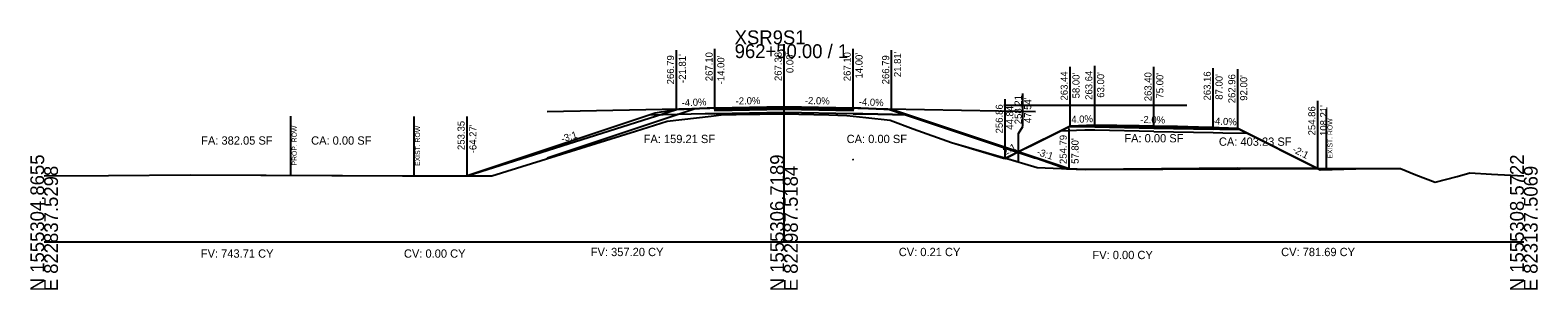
# Model space of a CAD drawing. Extents: x -26 to 823017, y -16 to 1558356.
# Drawn here: x 997.2 to 1302.8, y 1490.3 to 1542.8 of the extents above; entities that cross this region are included whole.
import ezdxf

# ---------------------------------------------------------------- set-up
doc = ezdxf.new("R2010")
doc.units = 0
for name, color, linetype in [('ASPHALT_19MM1', 7, 'Continuous'), ('ASPHALT_9_5MM1', 7, 'Continuous'), ('CONST_DCH', 7, 'Continuous'), ('CONST_LV3', 7, 'Continuous'), ('Default', 7, 'Continuous'), ('Draft_XS_Grid', 7, 'Continuous'), ('DTM_CORRIDOR', 7, 'Continuous'), ('DTM_P_FINISHED_GRADE2', 7, 'Continuous'), ('DTM_TEMP_DROP', 7, 'Continuous'), ('DTM_X_GROUND', 7, 'Continuous'), ('PROFILES_DCH_2', 7, 'Continuous'), ('SLOPE_STAKES_FILL', 7, 'Continuous'), ('XS_CELL', 7, 'Continuous'), ('XS_M_SHAPES_EARTHWORK', 7, 'Continuous'), ('XS_P_ASPHALT', 7, 'Continuous'), ('XS_P_DR_GRAVEL', 7, 'Continuous'), ('XS_P_GROUND', 7, 'Continuous'), ('XS_P_NULL_POINT', 7, 'Continuous'), ('XS_P_ROW', 7, 'Continuous'), ('XS_P_SHOULDER', 7, 'Continuous'), ('XS_P_SUBGRADE_GRANULAR', 7, 'Continuous'), ('XS_P_SUBGRADE_MILLING', 7, 'Continuous'), ('XS_P_SUBGRADE_UNDERCUT', 7, 'Continuous'), ('XS_P_TX_CLEARZONE', 7, 'Continuous'), ('XS_P_TX_FS_BS', 7, 'Continuous'), ('XS_SHEET_EW_TX_AREA', 7, 'Continuous'), ('XS_SHEET_EW_TX_VOLUME', 7, 'Continuous'), ('XS_X_ROW', 7, 'Continuous')]:
    doc.layers.add(name, color=color, linetype=linetype)

msp = doc.modelspace()

# ---------------------------------------------------------------- linework, layer by layer
at = {"layer": 'ASPHALT_19MM1'}
for points in [[(1136, 1526.81), (1136, 1526.6), (1150, 1526.88), (1150, 1526.88), (1150, 1526.88), (1164, 1526.6), (1164, 1526.81), (1164, 1526.81), (1150, 1527.09), (1150, 1527.09), (1150, 1527.09), (1136, 1526.81), (1136, 1526.81)], [(1213, 1523.27), (1225, 1523.03), (1237, 1522.79), (1237, 1523), (1225, 1523.24), (1213, 1523.48), (1213, 1523.27)]]:
    msp.add_lwpolyline(points, dxfattribs=at)
at = {"layer": 'ASPHALT_9_5MM1'}
msp.add_lwpolyline([(1136, 1527.1), (1150, 1527.38), (1150, 1527.38), (1150, 1527.38), (1164, 1527.1), (1164, 1526.98), (1150, 1527.26), (1150, 1527.26), (1150, 1527.26), (1136, 1526.98), (1136, 1527.1)], dxfattribs=at)
at = {"layer": 'CONST_DCH'}
msp.add_lwpolyline([(1213, 1523.48), (1225, 1523.24), (1237, 1523), (1237, 1523.16), (1225, 1523.4), (1213, 1523.64), (1213, 1523.48)], dxfattribs=at)
at = {"layer": 'CONST_LV3'}
for points in [[(1102, 1526.42), (1132, 1527.02), (1150, 1527.38), (1171, 1526.96), (1201, 1526.36)], [(1102, 1517.02), (1132, 1527.02), (1150, 1527.38), (1171, 1526.96), (1201, 1516.96)], [(1150, 1527.38), (1164, 1527.1)], [(1171.81, 1526.79), (1164, 1527.1), (1164, 1527.1)], [(1194.57, 1527.66), (1200.1, 1527.66), (1200.59, 1527.66), (1201.19, 1527.66), (1210.95, 1527.66), (1219.11, 1527.66), (1221.3, 1527.66), (1223.92, 1527.66), (1231.65, 1527.66)], [(1194.84, 1516.86), (1198.45, 1518.67), (1208, 1523.44), (1211.75, 1523.59), (1213, 1523.64)], [(1197.54, 1518.21), (1197.54, 1518.21), (1198.31, 1518.6), (1198.45, 1518.67), (1200.16, 1519.52), (1208, 1523.44), (1211.75, 1523.59), (1213, 1523.64), (1222.01, 1523.46), (1225, 1523.4), (1234.01, 1523.22), (1237, 1523.16), (1238.25, 1523.11), (1242, 1522.96), (1254.19, 1516.87), (1254.93, 1516.5), (1258.7, 1514.61), (1265.93, 1514.82), (1274.99, 1514.83), (1278.07, 1513.6), (1282.03, 1512.07), (1286.46, 1513.24), (1289.08, 1513.97), (1293.43, 1513.72), (1300, 1513.35)], [(1242, 1522.96), (1258.21, 1514.86)], [(1164, 1516.55), (1164, 1516.7), (1164, 1516.66)], [(1000, 1513.37), (1013.03, 1513.44), (1029.61, 1513.55), (1072.62, 1513.39), (1075.9, 1513.38), (1085.73, 1513.35)]]:
    msp.add_lwpolyline(points, dxfattribs=at)
at = {"layer": 'Default'}
msp.add_lwpolyline([(1136, 1526.98), (1150, 1527.26), (1150, 1527.26), (1150, 1527.26), (1164, 1526.98), (1164, 1526.81), (1150, 1527.09), (1150, 1527.09), (1150, 1527.09), (1136, 1526.81), (1136, 1526.98)], dxfattribs=at)
at = {"layer": 'DTM_P_FINISHED_GRADE2'}
msp.add_lwpolyline([(1085.73, 1513.35), (1128.19, 1526.79), (1136, 1527.1), (1150, 1527.38), (1164, 1527.1), (1171.81, 1526.79), (1197.54, 1518.21)], dxfattribs=at)
at = {"layer": 'DTM_X_GROUND'}
for points in [[(1000, 1513.37), (1013.03, 1513.44), (1029.61, 1513.55), (1072.62, 1513.37), (1075.9, 1513.36), (1085.73, 1513.35), (1128.19, 1526.79), (1128.19, 1526.79), (1128.19, 1526.79), (1128.19, 1526.79), (1128.19, 1526.79), (1128.19, 1526.79), (1136, 1527.1), (1136, 1527.1), (1136, 1527.1), (1150, 1527.38), (1164, 1527.1), (1164, 1527.1), (1164, 1527.1), (1171.81, 1526.79), (1171.81, 1526.79), (1171.81, 1526.79), (1171.81, 1526.79), (1171.81, 1526.79), (1171.81, 1526.79), (1171.81, 1526.79), (1171.81, 1526.79), (1197.54, 1518.21), (1197.54, 1518.21), (1198.31, 1518.6), (1198.45, 1518.67), (1200.16, 1519.52), (1208, 1523.44), (1211.75, 1523.59), (1213, 1523.64), (1222.01, 1523.46), (1225, 1523.4), (1234.01, 1523.22), (1237, 1523.16), (1238.25, 1523.11), (1242, 1522.96), (1254.19, 1516.87), (1254.93, 1516.5), (1258.7, 1514.61), (1265.93, 1514.82), (1274.99, 1514.83), (1278.07, 1513.6), (1282.03, 1512.07), (1286.46, 1513.24), (1289.08, 1513.97), (1293.43, 1513.72), (1300, 1513.35)], [(1000, 1513.37), (1013.03, 1513.44), (1029.61, 1513.55), (1075.9, 1513.38), (1088.73, 1513.34), (1089.99, 1513.34), (1090.77, 1513.34), (1119.87, 1522.39), (1126.32, 1524.45), (1135.22, 1525.46), (1137.29, 1525.7), (1140.32, 1525.75), (1149.96, 1525.93), (1159.11, 1525.69), (1162.75, 1525.61), (1166.59, 1525.18), (1171.51, 1524.63), (1176.18, 1522.89), (1183.99, 1520.12), (1194.47, 1517.1), (1201.34, 1515.07), (1211.12, 1514.65), (1241.88, 1514.91), (1274.99, 1514.83), (1278.07, 1513.6), (1282.03, 1512.07), (1286.46, 1513.24), (1289.08, 1513.97), (1293.43, 1513.72), (1300, 1513.35)], [(1000, 1513.37), (1013.03, 1513.44), (1029.61, 1513.55), (1075.9, 1513.38), (1088.73, 1513.34), (1089.99, 1513.34), (1090.77, 1513.34), (1119.87, 1522.39), (1126.32, 1524.45), (1135.22, 1525.46), (1137.29, 1525.7), (1140.32, 1525.75), (1149.96, 1525.93), (1159.11, 1525.69), (1162.75, 1525.61), (1166.59, 1525.18), (1171.51, 1524.63), (1176.18, 1522.89), (1183.99, 1520.12), (1190.24, 1518.23), (1194.47, 1516.97), (1194.84, 1516.86), (1198.31, 1518.6), (1198.45, 1518.67), (1208, 1523.44), (1211.75, 1523.59), (1213, 1523.64), (1222.01, 1523.46), (1225, 1523.4), (1234.01, 1523.22), (1237, 1523.16), (1238.25, 1523.11), (1242, 1522.96), (1254.19, 1516.87), (1254.93, 1516.5), (1258.7, 1514.61), (1265.93, 1514.82), (1274.99, 1514.83), (1278.07, 1513.6), (1282.03, 1512.07), (1286.46, 1513.24), (1289.08, 1513.97), (1293.43, 1513.72), (1300, 1513.35)]]:
    msp.add_lwpolyline(points, dxfattribs=at)
at = {"layer": 'XS_CELL'}
for p, q in [((1150, 1500), (1150, 1540)), ((1000, 1500), (1150, 1500)), ((1150, 1500), (1300, 1500))]:
    msp.add_line(p, q, dxfattribs=at)
at = {"layer": 'XS_M_SHAPES_EARTHWORK'}
msp.add_lwpolyline([(1085.73, 1513.35), (1088.73, 1513.34), (1089.99, 1513.34), (1090.77, 1513.34), (1119.87, 1522.39), (1126.32, 1524.45), (1135.22, 1525.46), (1137.29, 1525.7), (1140.32, 1525.75), (1149.96, 1525.93), (1159.11, 1525.69), (1162.75, 1525.61), (1166.59, 1525.18), (1171.51, 1524.63), (1176.18, 1522.89), (1183.99, 1520.12), (1194.47, 1517.1), (1197.54, 1516.19), (1197.54, 1518.21), (1175.03, 1525.71), (1166, 1525.9), (1164, 1525.94), (1150, 1526.22), (1136, 1525.94), (1134, 1525.9), (1122.69, 1525.67)], close=True, dxfattribs=at)
at = {"layer": 'XS_P_DR_GRAVEL'}
for points in [[(1211.75, 1523.59), (1208, 1523.44), (1207.96, 1523.42), (1207.86, 1523.37), (1209.14, 1523.34), (1213, 1523.27), (1213, 1523.55), (1213, 1523.64), (1211.75, 1523.59)], [(1238.25, 1523.11), (1242, 1522.96), (1242.14, 1522.89), (1242.57, 1522.68), (1238.39, 1522.76), (1237, 1522.79), (1237, 1523.07), (1237, 1523.16), (1238.25, 1523.11)]]:
    msp.add_lwpolyline(points, dxfattribs=at)
at = {"layer": 'XS_P_GROUND'}
for points in [[(1128.19, 1526.79), (1123.9, 1526.08), (1085.73, 1513.35)], [(1197.54, 1518.21), (1171.81, 1526.79), (1171.81, 1526.79)], [(1207.8, 1514.79), (1171.81, 1526.79), (1171.81, 1526.79)], [(1208, 1523.44), (1194.84, 1516.86)], [(1242, 1522.96), (1258.7, 1514.61)], [(1258.21, 1514.87), (1241.88, 1514.91), (1241.88, 1514.91), (1211.12, 1514.65), (1211.12, 1514.65), (1207.8, 1514.79)], [(1207.8, 1514.79), (1211.12, 1514.65), (1211.12, 1514.65), (1241.88, 1514.91), (1241.88, 1514.91), (1258.21, 1514.87)]]:
    msp.add_lwpolyline(points, dxfattribs=at)
at = {"layer": 'XS_P_ROW'}
msp.add_line((1050, 1513.47), (1050, 1525.47), dxfattribs=at)
at = {"layer": 'XS_P_SHOULDER'}
for points in [[(1136, 1527.1), (1128.19, 1526.79)], [(1164, 1527.1), (1171.81, 1526.79)], [(1208, 1523.44), (1211.75, 1523.59), (1213, 1523.64)], [(1242, 1522.96), (1238.25, 1523.11), (1237, 1523.16)]]:
    msp.add_lwpolyline(points, dxfattribs=at)
at = {"layer": 'XS_P_SUBGRADE_GRANULAR'}
for points in [[(1136, 1525.94), (1134, 1525.9), (1122.69, 1525.67)], [(1136, 1525.94), (1150, 1526.22), (1150, 1526.22)], [(1164, 1525.94), (1150, 1526.22), (1150, 1526.22)], [(1164, 1525.94), (1166, 1525.9), (1175.03, 1525.71)], [(1213, 1522.6), (1211, 1522.64), (1206, 1522.44)], [(1225, 1522.36), (1213, 1522.6)], [(1225, 1522.36), (1237, 1522.12)], [(1237, 1522.12), (1239, 1522.08), (1243.96, 1521.98)]]:
    msp.add_lwpolyline(points, dxfattribs=at)
at = {"layer": 'XS_P_SUBGRADE_UNDERCUT'}
msp.add_lwpolyline([(1207.33, 1514.82), (1211.12, 1514.65), (1258.18, 1514.87), (1242, 1522.96), (1238.25, 1523.11), (1234.01, 1523.22), (1229.77, 1523.33), (1225, 1523.4), (1222.01, 1523.46), (1213, 1523.64), (1208, 1523.44), (1197.54, 1518.21)], close=True, dxfattribs=at)
at = {"layer": 'XS_P_TX_CLEARZONE'}
for p, q in [((1128.19, 1526.79), (1128.19, 1538.79)), ((1136, 1527.1), (1136, 1539.1)), ((1150, 1527.38), (1150, 1539.38)), ((1164, 1527.1), (1164, 1539.1)), ((1171.81, 1526.79), (1171.81, 1538.79)), ((1208, 1523.44), (1208, 1535.44)), ((1213, 1523.64), (1213, 1535.64)), ((1225, 1523.4), (1225, 1535.4)), ((1237, 1523.16), (1237, 1535.16)), ((1242, 1522.96), (1242, 1534.96)), ((1194.84, 1516.86), (1194.84, 1528.86)), ((1198.4, 1523.35), (1198.4, 1530.02)), ((1258.21, 1514.86), (1258.21, 1528.56)), ((1085.73, 1513.35), (1085.73, 1525.35)), ((1197.54, 1521.97), (1198.4, 1523.35)), ((1198.4, 1523.35), (1198.4, 1523.35)), ((1207.8, 1514.79), (1207.8, 1522.92)), ((1197.54, 1518.21), (1197.54, 1521.97))]:
    msp.add_line(p, q, dxfattribs=at)
at = {"layer": 'XS_X_ROW'}
for p, q in [((1075, 1513.37), (1075, 1525.37)), ((1260, 1514.87), (1260, 1526.87))]:
    msp.add_line(p, q, dxfattribs=at)

# ---------------------------------------------------------------- texts
at = {"layer": 'CONST_DCH'}
for p in [(1194.76, 1516.74), (1258.13, 1514.74), (1258.62, 1514.49)]:
    msp.add_text('X', height=0.24, dxfattribs=at).set_placement(p)
at = {"layer": 'Draft_XS_Grid'}
msp.add_text('-', height=0.0001, dxfattribs=at).set_placement((1000, 1500))
at = {"layer": 'DTM_CORRIDOR'}
for p in [(1212.92, 1523.52), (1224.92, 1523.28), (1236.92, 1523.04)]:
    msp.add_text('X', height=0.24, dxfattribs=at).set_placement(p)
at = {"layer": 'DTM_TEMP_DROP'}
for p in [(1135.92, 1526.98), (1149.92, 1527.26), (1163.92, 1526.98)]:
    msp.add_text('X', height=0.24, dxfattribs=at).set_placement(p)
at = {"layer": 'PROFILES_DCH_2'}
for p in [(1171.73, 1526.67), (1207.73, 1514.67), (1258.13, 1514.74)]:
    msp.add_text('X', height=0.24, dxfattribs=at).set_placement(p)
at = {"layer": 'SLOPE_STAKES_FILL'}
for p in [(1197.46, 1518.09), (1085.65, 1513.23)]:
    msp.add_text('X', height=0.24, dxfattribs=at).set_placement(p)
at = {"layer": 'XS_CELL'}
for s, p in [('XSR9S1', (1140, 1540)), ('962+50.00 / 1', (1140, 1537.2))]:
    msp.add_text(s, height=2.8, dxfattribs=at).set_placement(p)
for s, p in [('N 1555304.8655', (1000, 1490)), ('N 1555306.7189', (1150, 1490)), ('N 1555308.5722', (1300, 1490)), ('E 822837.5298', (1002.8, 1490)), ('E 822987.5184', (1152.8, 1490)), ('E 823137.5069', (1302.8, 1490))]:
    msp.add_text(s, height=2.8, rotation=90, dxfattribs=at).set_placement(p)
at = {"layer": 'XS_P_ASPHALT'}
for p in [(1194.76, 1516.74), (1258.62, 1514.49)]:
    msp.add_text('X', height=0.24, dxfattribs=at).set_placement(p)
at = {"layer": 'XS_P_NULL_POINT'}
for p in [(1197.46, 1518.09), (1085.65, 1513.23)]:
    msp.add_text('X', height=0.24, dxfattribs=at).set_placement(p)
at = {"layer": 'XS_P_ROW'}
msp.add_text('PROP. ROW', height=1, rotation=90, dxfattribs=at).set_placement((1051.2, 1515.47))
at = {"layer": 'XS_P_SHOULDER'}
for p in [(1207.92, 1523.32), (1241.92, 1522.84)]:
    msp.add_text('X', height=0.24, dxfattribs=at).set_placement(p)
at = {"layer": 'XS_P_SUBGRADE_MILLING'}
for p in [(1128.11, 1526.67), (1171.73, 1526.67)]:
    msp.add_text('X', height=0.24, dxfattribs=at).set_placement(p)
at = {"layer": 'XS_P_TX_CLEARZONE'}
for s, p in [('266.79', (1127.71, 1531.89)), ("-21.81'", (1130.11, 1532.17)), ('267.10', (1135.52, 1532.52)), ("-14.00'", (1137.92, 1531.89)), ('267.38', (1149.52, 1532.56)), ("0.00'", (1151.92, 1534.17)), ('267.10', (1163.52, 1532.52)), ("14.00'", (1165.92, 1533.07)), ('266.79', (1171.33, 1531.89)), ("21.81'", (1173.73, 1533.35)), ('263.64', (1212.52, 1528.75)), ('263.44', (1207.52, 1528.62)), ("58.00'", (1209.92, 1529.05)), ("63.00'", (1214.92, 1529.18)), ('263.40', (1224.52, 1528.46)), ("75.00'", (1226.92, 1529.01)), ('263.16', (1236.52, 1528.62)), ("87.00'", (1238.92, 1528.77)), ('262.96', (1241.52, 1528.06)), ("92.00'", (1243.92, 1528.57)), ('258.21', (1198.18, 1523.82)), ("47.54'", (1200.12, 1524.05)), ('256.86', (1194.36, 1521.96)), ("44.84'", (1196.48, 1522.7)), ('254.86', (1257.73, 1521.56)), ("108.21'", (1260.13, 1521.44)), ('253.35', (1085.25, 1518.6)), ("-64.27'", (1087.65, 1517.94)), ('254.79', (1207.32, 1515.76)), ("57.80'", (1209.72, 1515.79))]:
    msp.add_text(s, height=1.44, rotation=90, dxfattribs=at).set_placement(p)
at = {"layer": 'XS_P_TX_FS_BS'}
for s, rotation, p in [('-4.0%', 2.2906, (1129.28, 1527.43)), ('-2.0%', 1.1458, (1140.2, 1527.79)), ('-2.0%', 358.8542, (1154.22, 1527.9)), ('-4.0%', 357.7094, (1165.14, 1527.66)), ('4.0%', 2.2906, (1208.27, 1524.05)), ('-2.0%', 358.8542, (1222.22, 1524.06)), ('-3:1', 17.5613, (1105.05, 1520.1)), ('-4.0%', 357.7094, (1236.73, 1523.77)), ('2:1', 26.5651, (1194.83, 1517.53)), ('-3:1', 341.5607, (1201.14, 1517.64)), ('-2:1', 333.4349, (1252.95, 1518.25))]:
    msp.add_text(s, height=1.44, rotation=rotation, dxfattribs=at).set_placement(p)
at = {"layer": 'XS_SHEET_EW_TX_AREA'}
for s, p in [('FA: 382.05 SF', (1031.83, 1519.68)), ('CA: 0.00 SF', (1054.12, 1519.68)), ('FA: 159.21 SF', (1121.54, 1520)), ('CA: 0.00 SF', (1162.7, 1520)), ('FA: 0.00 SF', (1219, 1520.14)), ('CA: 403.23 SF', (1238.17, 1519.45))]:
    msp.add_text(s, height=1.68, dxfattribs=at).set_placement(p)
at = {"layer": 'XS_SHEET_EW_TX_VOLUME'}
for s, p in [('FV: 743.71 CY', (1031.76, 1496.8)), ('CV: 0.00 CY', (1072.94, 1496.8)), ('FV: 357.20 CY', (1110.82, 1497.12)), ('CV: 0.21 CY', (1173.27, 1497.12)), ('FV: 0.00 CY', (1212.54, 1496.51)), ('CV: 781.69 CY', (1250.79, 1497.12))]:
    msp.add_text(s, height=1.68, dxfattribs=at).set_placement(p)
at = {"layer": 'XS_X_ROW'}
for p in [(1076.2, 1515.37), (1261.2, 1516.87)]:
    msp.add_text('EXIST. ROW', height=1, rotation=90, dxfattribs=at).set_placement(p)

doc.saveas('drawing.dxf')
